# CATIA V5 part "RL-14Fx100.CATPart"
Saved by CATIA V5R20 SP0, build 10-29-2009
Part number: _RL-14Fx100
Definition: NONE
Nomenclature: _RL-14Fx100
Source: Unknown
Description: PART-_RL-14Fx100-DESC
Bounding box of the stored display mesh (mm): x -100 to 12.5, y -7.8 to 7.8, z -7.8 to 7.8
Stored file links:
  C:\Users\Utente\Desktop\IO LAVORO\3D X SITO CF\X SITO\PLASTICA\RLF\RL-14Fx100.CATPart
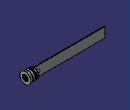
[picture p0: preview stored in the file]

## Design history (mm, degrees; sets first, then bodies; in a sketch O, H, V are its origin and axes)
Body1 "_RL-14Fx100" (main body)
  Solid1: solid without history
